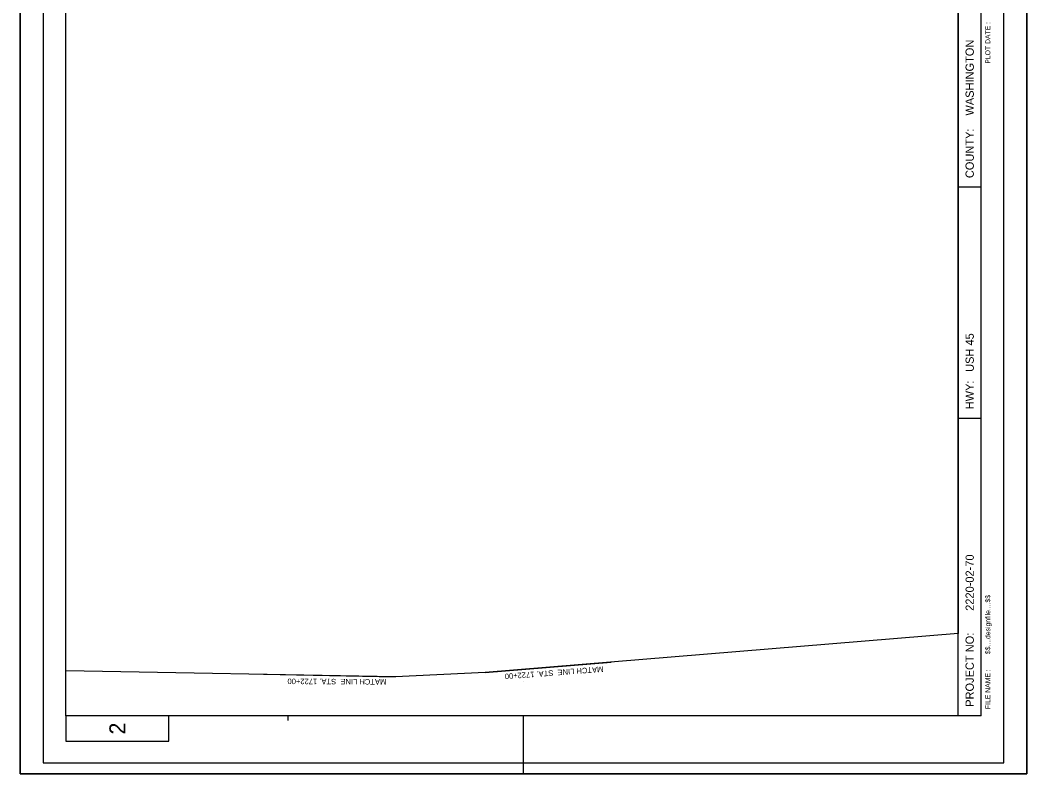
# Model space of a CAD drawing. Extents: x 361080 to 362180, y 131293 to 132993.
# Drawn here: x 361080 to 362180, y 131293 to 132116 of the extents above; entities that cross this region are included whole.
import ezdxf

# ---------------------------------------------------------------- set-up
doc = ezdxf.new("R2010")
doc.units = 0
for name, color, linetype in [('Default', 7, 'Continuous'), ('P_SHTIDX_2 [KAPUR_CADDS_LEVELS]', 7, 'Continuous'), ('P_SHTIDX_3 [KAPUR_CADDS_LEVELS]', 7, 'Continuous'), ('P_SHTIDX_4 [KAPUR_CADDS_LEVELS]', 7, 'Continuous'), ('P_TXT_Plan 2 [KAPUR_CADDS_LEVELS]', 7, 'Continuous'), ('P_TXT_Plan 3 [KAPUR_CADDS_LEVELS]', 7, 'Continuous'), ('P_TXT_Plan 4 [KAPUR_CADDS_LEVELS]', 7, 'Continuous')]:
    doc.layers.add(name, color=color, linetype=linetype)

msp = doc.modelspace()

# ---------------------------------------------------------------- linework, layer by layer
at = {"layer": 'Default'}
msp.add_lwpolyline([(362105.1, 131446.1), (361588.3, 131403.7), (361490.1, 131398.9), (361130.1, 131405.5), (361130.1, 132906.6), (361506.5, 132898.2), (361509.7, 132902.2), (361861.9, 132931.1), (362105.1, 132931.1)], close=True, dxfattribs=at)
msp.add_lwpolyline([(362105.1, 131446.1), (361588.3, 131403.7), (361490.1, 131398.9), (361130.1, 131405.5), (361130.1, 132906.6), (361506.5, 132898.2), (361509.7, 132902.2), (361861.9, 132931.1), (362105.1, 132931.1)], close=True, dxfattribs=at)
msp.add_lwpolyline([(362105.1, 131446.1), (361588.3, 131403.7), (361490.1, 131398.9), (361130.1, 131405.5), (361130.1, 132906.6), (361506.5, 132898.2), (361509.7, 132902.2), (361861.9, 132931.1), (362105.1, 132931.1)], close=True, dxfattribs=at)
msp.add_lwpolyline([(362105.1, 131446.1), (361588.3, 131403.7), (361490.1, 131398.9), (361130.1, 131405.5), (361130.1, 132906.6), (361506.5, 132898.2), (361509.7, 132902.2), (361861.9, 132931.1), (362105.1, 132931.1)], close=True, dxfattribs=at)
msp.add_lwpolyline([(362105.1, 131446.1), (361588.3, 131403.7), (361490.1, 131398.9), (361130.1, 131405.5), (361130.1, 132906.6), (361506.5, 132898.2), (361509.7, 132902.2), (361861.9, 132931.1), (362105.1, 132931.1)], close=True, dxfattribs=at)
msp.add_lwpolyline([(362105.1, 131446.1), (361588.3, 131403.7), (361490.1, 131398.9), (361130.1, 131405.5), (361130.1, 132906.6), (361506.5, 132898.2), (361509.7, 132902.2), (361861.9, 132931.1), (362105.1, 132931.1)], close=True, dxfattribs=at)
msp.add_lwpolyline([(362105.1, 131446.1), (361588.3, 131403.7), (361490.1, 131398.9), (361130.1, 131405.5), (361130.1, 132906.6), (361506.5, 132898.2), (361509.7, 132902.2), (361861.9, 132931.1), (362105.1, 132931.1)], close=True, dxfattribs=at)
msp.add_lwpolyline([(362105.1, 131446.1), (361588.3, 131403.7), (361490.1, 131398.9), (361130.1, 131405.5), (361130.1, 132906.6), (361506.5, 132898.2), (361509.7, 132902.2), (361861.9, 132931.1), (362105.1, 132931.1)], close=True, dxfattribs=at)
at = {"layer": 'P_SHTIDX_2 [KAPUR_CADDS_LEVELS]'}
msp.add_lwpolyline([(361080.1, 131292.8), (361080.1, 132992.8), (362180.1, 132992.8), (362180.1, 131292.8), (361080.1, 131292.8)], dxfattribs=at)
at = {"layer": 'P_SHTIDX_3 [KAPUR_CADDS_LEVELS]'}
for p, q in [((361130.1, 131356.1), (361130.1, 132931.1)), ((362105.1, 131356.1), (362105.1, 132931.1)), ((362130.1, 131356.1), (362130.1, 132931.1)), ((362130.1, 131933.6), (362105.1, 131933.6)), ((362130.1, 131681.1), (362105.1, 131681.1)), ((361630.1, 131393.6), (361630.1, 131393.6)), ((362130.1, 131356.1), (361130.1, 131356.1)), ((361372.6, 131356.1), (361372.6, 131351.1)), ((361630.1, 131292.8), (361630.1, 131356.1)), ((361080.1, 131292.8), (361080.1, 131342.8)), ((362180.1, 131292.8), (362180.1, 131342.8)), ((361130.1, 131292.8), (361080.1, 131292.8)), ((361655.1, 131292.8), (361605.1, 131292.8)), ((362180.1, 131292.8), (362130.1, 131292.8))]:
    msp.add_line(p, q, dxfattribs=at)
msp.add_lwpolyline([(361130.1, 131356.1), (361130.1, 131328.6), (361242.6, 131328.6), (361242.6, 131356.1)], close=True, dxfattribs=at)
at = {"layer": 'P_SHTIDX_4 [KAPUR_CADDS_LEVELS]'}
for points in [[(362180.1, 131292.8), (362180.1, 132992.8), (361080.1, 132992.8), (361080.1, 131292.8)], [(362155.1, 131304.8), (362155.1, 132959.8), (361105.1, 132959.8), (361105.1, 131304.8)]]:
    msp.add_lwpolyline(points, close=True, dxfattribs=at)
at = {"layer": 'P_TXT_Plan 3 [KAPUR_CADDS_LEVELS]'}
for p, q in [((361588.3, 131403.7), (361726, 131415)), ((361346.1, 131401.6), (361490.1, 131398.9))]:
    msp.add_line(p, q, dxfattribs=at)
at = {"layer": 'P_TXT_Plan 4 [KAPUR_CADDS_LEVELS]'}
msp.add_lwpolyline([(361080.1, 131292.8), (361080.1, 132992.8), (362180.1, 132992.8), (362180.1, 131292.8)], close=True, dxfattribs=at)

# ---------------------------------------------------------------- texts
at = {"layer": 'P_SHTIDX_3 [KAPUR_CADDS_LEVELS]'}
for s, height, p in [('PLOT DATE :', 5.4, (362140.1, 132068.6)), (' WASHINGTON', 9, (362122.1, 132008.6)), ('COUNTY:', 9, (362122.1, 131943.6)), (' USH 45', 9, (362122.1, 131728.6)), ('HWY:', 9, (362122.1, 131691.1)), (' 2220-02-70', 9, (362122.1, 131467.6)), ('$$....designfile....$$', 5.4, (362140.1, 131423.6)), ('PROJECT NO:', 9, (362122.1, 131366.1)), ('FILE NAME :', 5.4, (362140.1, 131363.6)), ('2', 17.5, (361195.1, 131335.8))]:
    msp.add_text(s, height=height, rotation=90, dxfattribs=at).set_placement(p)
at = {"layer": 'P_TXT_Plan 2 [KAPUR_CADDS_LEVELS]'}
for rotation, p in [(184.2781, (361717.1, 131410.2)), (179.6776, (361480.2, 131396.3))]:
    msp.add_text('MATCH LINE  STA. 1722+00', height=6, rotation=rotation, dxfattribs=at).set_placement(p)

doc.saveas('drawing.dxf')
